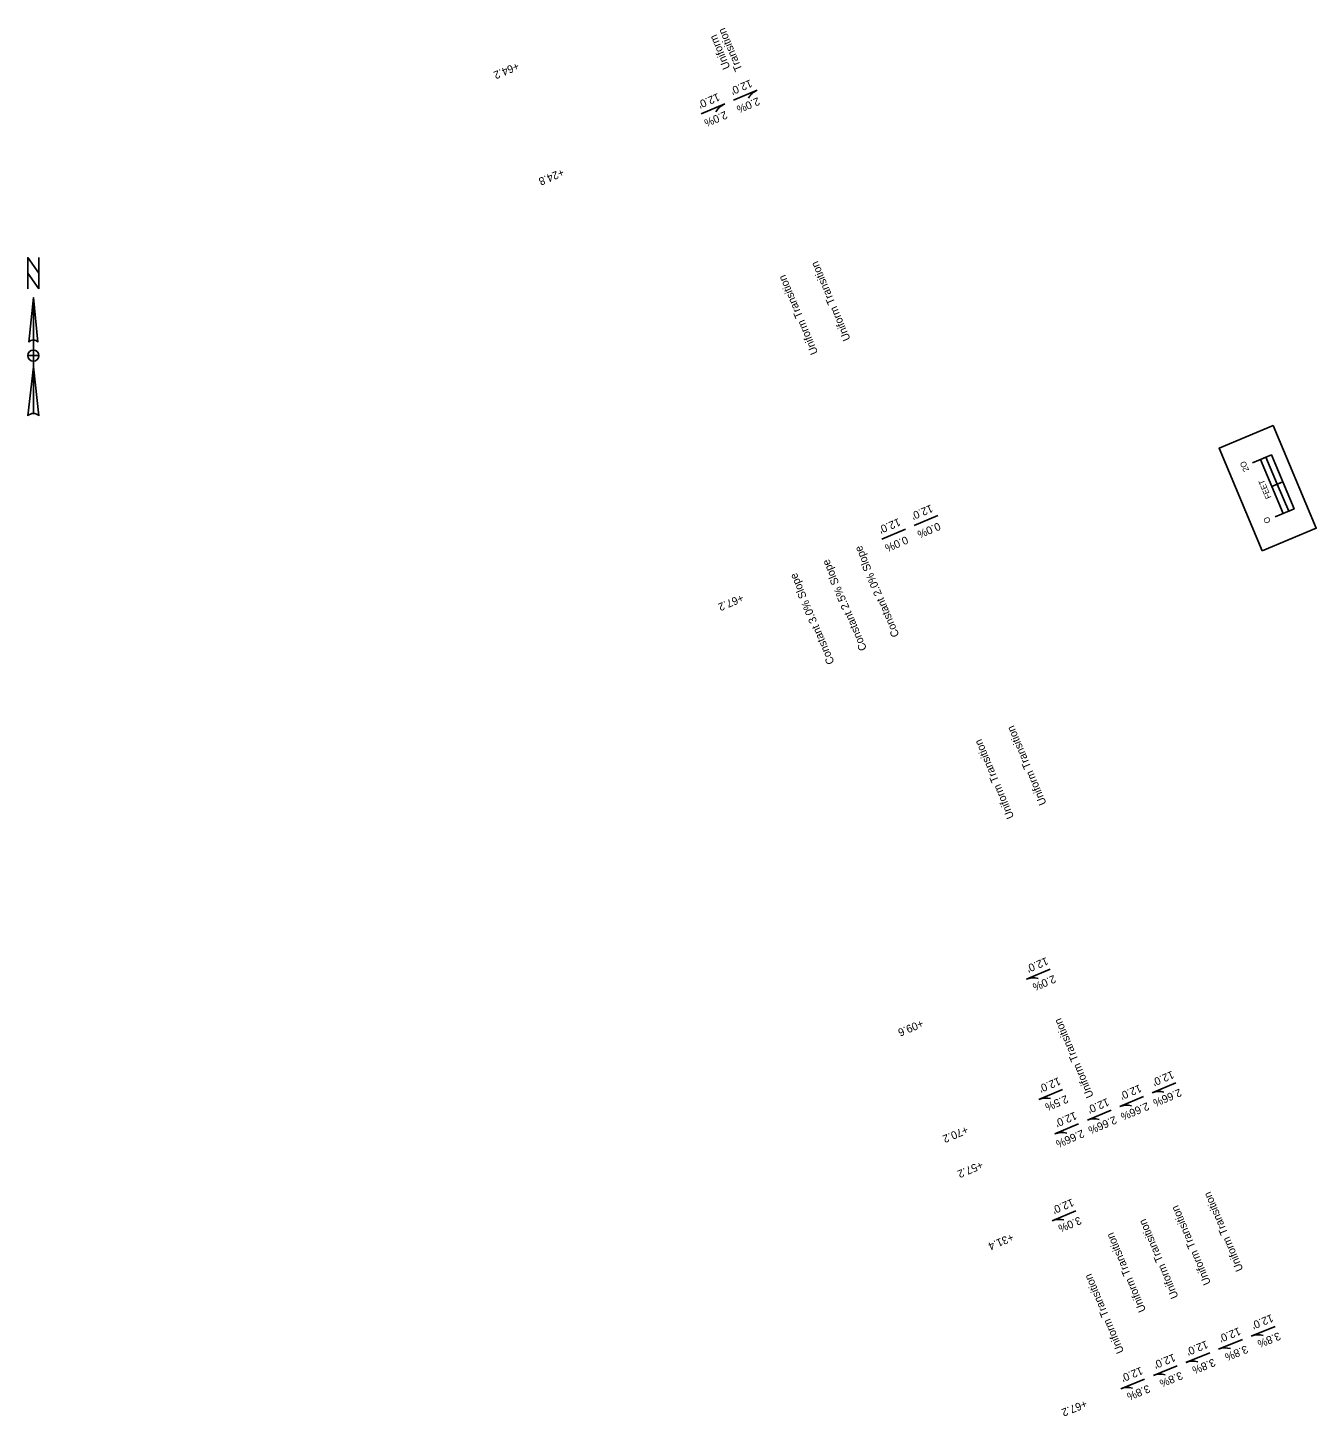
# Model space of a CAD drawing. Extents: x 20505195 to 20506806, y 7965197 to 7979043.
# Drawn here: x 20505849.4 to 20506288.9, y 7975477.4 to 7975951.2 of the extents above; entities that cross this region are included whole.
import ezdxf

# ---------------------------------------------------------------- set-up
doc = ezdxf.new("R2010")
doc.units = 0
doc.layers.add('Cell', color=7, linetype='Continuous')
doc.layers.add('SheetText', color=7, linetype='Continuous')

msp = doc.modelspace()

# ---------------------------------------------------------------- linework, layer by layer
at = {"layer": 'Cell'}
for p, q in [((20505851.35, 7975859.07), (20505852.87, 7975843.86)), ((20505851.35, 7975859.07), (20505851.35, 7975819.52)), ((20505849.83, 7975843.86), (20505849.83, 7975843.86)), ((20505849.89, 7975844), (20505850.17, 7975844.32)), ((20505851.35, 7975837.4), (20505851.35, 7975837.4)), ((20505849.45, 7975818.76), (20505851.35, 7975835.5))]:
    msp.add_line(p, q, dxfattribs=at)
msp.add_lwpolyline([(20505853.25, 7975862.12), (20505849.45, 7975867.44), (20505849.45, 7975872.76), (20505853.25, 7975867.44)], close=True, dxfattribs=at)
for points in [[(20505849.45, 7975862.12), (20505849.45, 7975872.76), (20505853.25, 7975867.44), (20505853.25, 7975872.76)], [(20505849.83, 7975843.86), (20505851.35, 7975859.07), (20505851.35, 7975844.62)], [(20505853.25, 7975839.3), (20505851.35, 7975839.3), (20505851.35, 7975841.2)], [(20505851.35, 7975837.4), (20505851.35, 7975839.3), (20505849.45, 7975839.3)], [(20505851.35, 7975819.52), (20505851.35, 7975835.5), (20505853.25, 7975818.76)]]:
    msp.add_lwpolyline(points, dxfattribs=at)
for centre, radius, start, end in [((20505851.35, 7975839.3), 1.9, 90, 180), ((20505851.35, 7975842.72), 1.9, 90.0204, 143.1257), ((20505851.35, 7975842.72), 1.9, 36.8481, 90.0218), ((20505851.35, 7975839.3), 1.9, 0, 90), ((20505851.35, 7975839.3), 1.9, 180, 270), ((20505851.35, 7975839.3), 1.9, 270, 360), ((20505851.35, 7975816.77), 2.76, 89.9894, 133.619), ((20505851.35, 7975816.77), 2.76, 46.4021, 90.0006)]:
    msp.add_arc(centre, radius, start, end, dxfattribs=at)
at = {"layer": 'SheetText'}
for p, q in [((20506090.13, 7975926.41), (20506098.21, 7975929.82)), ((20506079.07, 7975921.74), (20506087.15, 7975925.15)), ((20506277.48, 7975796.19), (20506273.79, 7975794.64)), ((20506277.48, 7975796.19), (20506273.79, 7975794.64)), ((20506151.76, 7975781.36), (20506159.85, 7975784.77)), ((20506140.71, 7975776.7), (20506148.79, 7975780.1)), ((20506198.13, 7975629.87), (20506190.05, 7975626.46)), ((20506241.03, 7975591.1), (20506232.95, 7975587.69)), ((20506202.36, 7975588.89), (20506194.28, 7975585.48)), ((20506229.97, 7975586.43), (20506221.89, 7975583.02)), ((20506218.92, 7975581.77), (20506210.84, 7975578.36)), ((20506207.86, 7975577.1), (20506199.78, 7975573.69)), ((20506206.89, 7975547.46), (20506198.79, 7975544.09)), ((20506274.87, 7975508.01), (20506266.74, 7975504.73)), ((20506263.75, 7975503.52), (20506255.61, 7975500.24)), ((20506241.49, 7975494.54), (20506233.36, 7975491.26)), ((20506252.62, 7975499.03), (20506244.48, 7975495.75)), ((20506230.36, 7975490.05), (20506222.23, 7975486.76))]:
    msp.add_line(p, q, dxfattribs=at)
for points in [[(20506270.46, 7975772.63), (20506255.74, 7975807.66), (20506274.18, 7975815.41), (20506288.9, 7975780.37)], [(20506270.46, 7975772.63), (20506255.74, 7975807.66), (20506274.18, 7975815.41), (20506288.9, 7975780.37)], [(20506275.62, 7975795.41), (20506271.75, 7975804.63), (20506269.92, 7975803.86), (20506273.79, 7975794.64)], [(20506281.35, 7975786.97), (20506277.48, 7975796.19), (20506275.62, 7975795.41), (20506279.5, 7975786.19)]]:
    msp.add_lwpolyline(points, close=True, dxfattribs=at)
for points in [[(20506274.9, 7975784.26), (20506281.35, 7975786.97), (20506273.61, 7975805.41), (20506267.15, 7975802.69)], [(20506277.67, 7975785.42), (20506269.92, 7975803.86)]]:
    msp.add_lwpolyline(points, dxfattribs=at)
for centre, start, end in [((20506100.6, 7975924.14), 112.8763, 151.0793), ((20506089.55, 7975919.47), 112.8763, 151.0793), ((20506192.44, 7975620.78), 74.6732, 112.8763), ((20506196.68, 7975579.8), 74.6732, 112.8763), ((20506235.34, 7975582.01), 74.6748, 112.8779), ((20506224.29, 7975577.34), 74.6748, 112.8779), ((20506213.23, 7975572.68), 74.6748, 112.8779), ((20506202.18, 7975568.01), 74.6748, 112.8779), ((20506201.16, 7975538.4), 74.4039, 112.607), ((20506269.05, 7975499.01), 73.7765, 111.9795), ((20506257.92, 7975494.52), 73.7765, 111.9795), ((20506246.79, 7975490.03), 73.7765, 111.9795), ((20506235.66, 7975485.54), 73.7765, 111.9795), ((20506224.54, 7975481.05), 73.7765, 111.9795)]:
    msp.add_arc(centre, 6.16, start, end, dxfattribs=at)

# ---------------------------------------------------------------- texts
for s, height, rotation, p in [('Transition', 2.664, 112.7854, (20506093.21, 7975936.95)), ('Uniform', 2.664, 112.7854, (20506089.1, 7975937.6)), ('+64.2', 2.664, 202.8779, (20506016.36, 7975939.49)), ("12.0'", 2.664, 202.979, (20506095.85, 7975933.59)), ("12.0'", 2.664, 202.979, (20506084.8, 7975928.93)), ('2.0%', 2.664, 202.979, (20506098.43, 7975927.49)), ('2.0%', 2.664, 202.979, (20506087.37, 7975922.83)), ('+24.8', 2.664, 202.8779, (20506031.72, 7975903.21)), ('Uniform Transition', 2.664, 112.7854, (20506130.11, 7975844.92)), ('Uniform Transition', 2.664, 112.7854, (20506119.04, 7975840.27)), ('2O', 2, 112.7844, (20506266.03, 7975800.19)), ('FEET', 2, 112.7844, (20506273.63, 7975790.89)), ("12.0'", 2.664, 202.979, (20506157.49, 7975788.55)), ("12.0'", 2.664, 202.979, (20506146.44, 7975783.88)), ('O', 2, 112.7844, (20506273.44, 7975782.57)), ('0.0%', 2.664, 202.979, (20506160.06, 7975782.44)), ('Constant 2.0% Slope', 2.664, 112.8763, (20506146.76, 7975743.87)), ('0.0%', 2.664, 202.979, (20506149.01, 7975777.78)), ('Constant 2.5% Slope', 2.664, 112.8763, (20506135.7, 7975739.21)), ('Constant 3.0% Slope', 2.664, 112.8763, (20506124.64, 7975734.54)), ('+67.2', 2.664, 202.8779, (20506092.95, 7975757.99)), ('Uniform Transition', 2.664, 112.7854, (20506196.96, 7975686.47)), ('Uniform Transition', 2.664, 112.7854, (20506185.9, 7975681.82)), ("12.0'", 2.664, 202.979, (20506196.81, 7975634.08)), ('2.0%', 2.664, 202.979, (20506199.39, 7975627.98)), ('Uniform Transition', 2.664, 112.7854, (20506213.05, 7975586.61)), ('+09.6', 2.664, 202.8779, (20506154.27, 7975612.81)), ("12.0'", 2.664, 202.9806, (20506239.72, 7975595.31)), ("12.0'", 2.664, 202.979, (20506201.05, 7975593.11)), ("12.0'", 2.664, 202.9806, (20506228.66, 7975590.65)), ('2.5%', 2.664, 202.979, (20506203.62, 7975587)), ("12.0'", 2.664, 202.9806, (20506217.6, 7975585.98)), ('2.66%', 2.664, 202.9806, (20506231.23, 7975584.55)), ('2.66%', 2.664, 202.9806, (20506242.29, 7975589.21)), ("12.0'", 2.664, 202.9806, (20506206.55, 7975581.32)), ('2.66%', 2.664, 202.9806, (20506220.18, 7975579.88)), ('+70.2', 2.664, 202.8779, (20506169.53, 7975576.49)), ('2.66%', 2.664, 202.9806, (20506209.12, 7975575.22)), ('+57.2', 2.664, 202.8779, (20506174.59, 7975564.51)), ("12.0'", 2.664, 202.7097, (20506205.6, 7975551.68)), ('Uniform Transition', 2.664, 112.7854, (20506264.07, 7975527.41)), ('Uniform Transition', 2.664, 112.7854, (20506253.01, 7975522.76)), ('3.0%', 2.664, 202.7097, (20506208.14, 7975545.57)), ('Uniform Transition', 2.664, 112.7854, (20506241.95, 7975518.11)), ('+31.4', 2.664, 202.6086, (20506185.09, 7975539.82)), ('Uniform Transition', 2.664, 112.7854, (20506230.88, 7975513.47)), ('Uniform Transition', 2.664, 112.7854, (20506223.39, 7975499.4)), ("12.0'", 2.664, 202.0822, (20506273.63, 7975512.25)), ("12.0'", 2.664, 202.0822, (20506262.5, 7975507.76)), ('3.8%', 2.664, 202.0822, (20506276.11, 7975506.11)), ("12.0'", 2.664, 202.0822, (20506251.37, 7975503.27)), ('3.8%', 2.664, 202.0822, (20506264.98, 7975501.61)), ("12.0'", 2.664, 202.0822, (20506240.24, 7975498.78)), ('3.8%', 2.664, 202.0822, (20506253.85, 7975497.12)), ("12.0'", 2.664, 202.0822, (20506229.12, 7975494.28)), ('3.8%', 2.664, 202.0822, (20506242.72, 7975492.63)), ('3.8%', 2.664, 202.0822, (20506231.59, 7975488.14)), ('+67.2', 2.664, 201.9795, (20506210.13, 7975483.01))]:
    msp.add_text(s, height=height, rotation=rotation, dxfattribs=at).set_placement(p)

doc.saveas('drawing.dxf')
